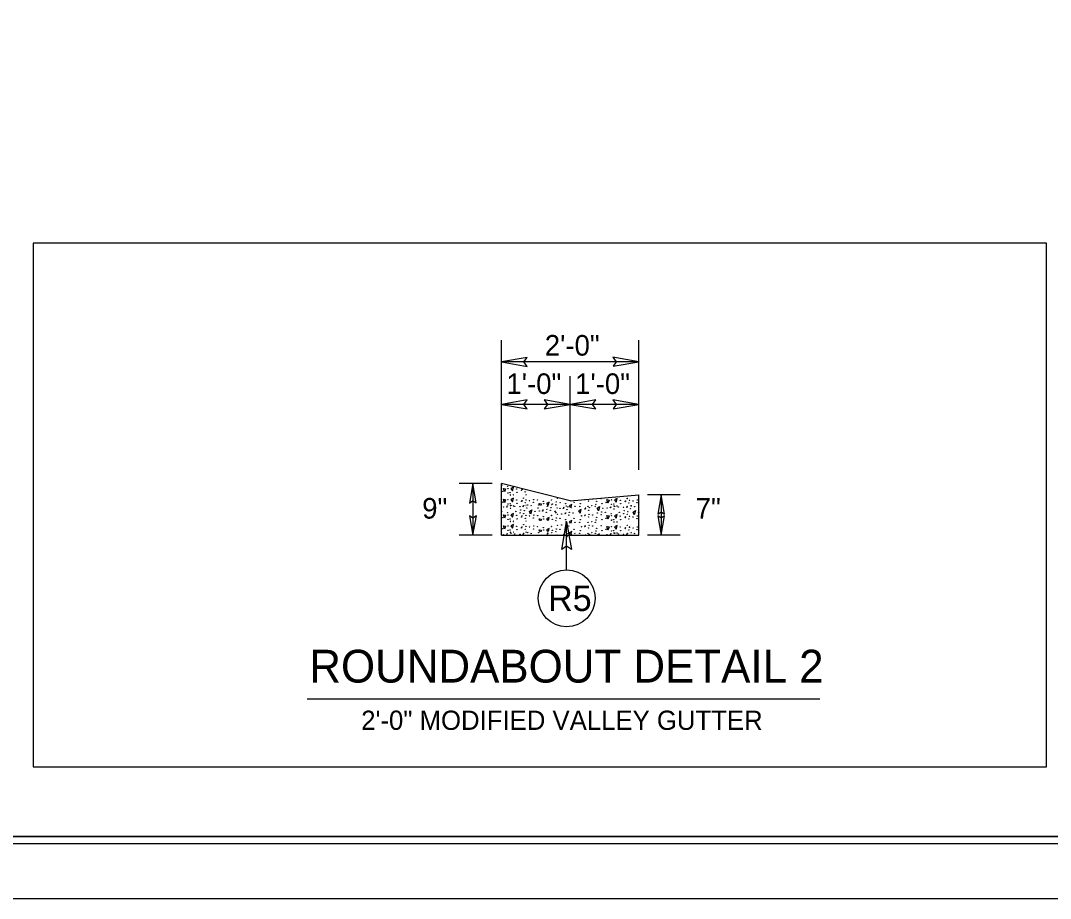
# Model space of a CAD drawing. Extents: x 1640342 to 1730599, y 538663 to 843747.
# Drawn here: x 1730007.8 to 1730082.7, y 538663.2 to 538727.1 of the extents above; entities that cross this region are included whole.
import ezdxf

# ---------------------------------------------------------------- set-up
doc = ezdxf.new("R2010")
doc.units = 0
for name, color, linetype in [('Default', 7, 'Continuous'), ('Sheet Plan CELL', 7, 'Continuous'), ('Sheet Plot Border Inside CELL', 7, 'Continuous'), ('Sheet Plot Border Outside CELL', 7, 'Continuous'), ('Typical Curb CELL', 7, 'Continuous'), ('Typical ID Circle CELL', 7, 'Continuous'), ('Typical Pavement Slope CELL', 7, 'Continuous'), ('Typical Terminator CELL', 7, 'Continuous'), ('Typical Text ID Circle CELL', 7, 'Continuous'), ('Typical Text Label CELL', 7, 'Continuous')]:
    doc.layers.add(name, color=color, linetype=linetype)

msp = doc.modelspace()

# ---------------------------------------------------------------- linework, layer by layer
at = {"layer": 'Default'}
for p, q in [((1730042.739, 538694.39), (1730042.739, 538703.839)), ((1730052.739, 538694.39), (1730052.739, 538703.839)), ((1730052.739, 538702.256), (1730042.739, 538702.256)), ((1730047.739, 538694.39), (1730047.739, 538701.218)), ((1730047.739, 538699.155), (1730042.739, 538699.155)), ((1730052.739, 538699.155), (1730047.739, 538699.155)), ((1730042.062, 538693.39), (1730039.673, 538693.39)), ((1730040.673, 538693.39), (1730040.673, 538689.64)), ((1730055.756, 538692.582), (1730053.367, 538692.582)), ((1730054.367, 538692.582), (1730054.367, 538689.64)), ((1730042.062, 538689.64), (1730039.673, 538689.64)), ((1730055.756, 538689.64), (1730053.367, 538689.64))]:
    msp.add_line(p, q, dxfattribs=at)
for points in [[(1730044.613, 538702.578), (1730042.739, 538702.256), (1730044.624, 538701.922), (1730044.384, 538702.256)], [(1730050.865, 538701.933), (1730052.739, 538702.256), (1730050.855, 538702.589), (1730051.094, 538702.256)], [(1730044.613, 538699.478), (1730042.739, 538699.155), (1730044.624, 538698.822), (1730044.384, 538699.155)], [(1730045.865, 538698.832), (1730047.739, 538699.155), (1730045.855, 538699.488), (1730046.094, 538699.155)], [(1730049.613, 538699.478), (1730047.739, 538699.155), (1730049.624, 538698.822), (1730049.384, 538699.155)], [(1730050.865, 538698.832), (1730052.739, 538699.155), (1730050.855, 538699.488), (1730051.094, 538699.155)], [(1730040.915, 538691.984), (1730040.673, 538693.39), (1730040.423, 538691.977), (1730040.673, 538692.156)], [(1730054.609, 538691.176), (1730054.367, 538692.582), (1730054.117, 538691.168), (1730054.367, 538691.348)], [(1730040.431, 538691.041), (1730040.673, 538689.635), (1730040.923, 538691.049), (1730040.673, 538690.869)], [(1730054.125, 538691.041), (1730054.367, 538689.635), (1730054.617, 538691.049), (1730054.367, 538690.869)]]:
    msp.add_lwpolyline(points, close=True, dxfattribs=at)
at = {"layer": 'Sheet Plan CELL'}
for points in [[(1729873.99, 538667.718), (1729873.985, 538877.713), (1730133.983, 538877.721), (1730133.985, 538847.708), (1730173.993, 538847.706), (1730173.993, 538667.718)], [(1730173.998, 538877.718), (1729873.99, 538877.718), (1729873.99, 538667.718), (1730173.993, 538667.718)]]:
    msp.add_lwpolyline(points, close=True, dxfattribs=at)
at = {"layer": 'Sheet Plot Border Inside CELL'}
msp.add_lwpolyline([(1729843.293, 538667.216), (1730176.49, 538667.218), (1730176.493, 538878.216), (1729843.293, 538878.216)], close=True, dxfattribs=at)
at = {"layer": 'Sheet Plot Border Outside CELL'}
msp.add_lwpolyline([(1729840.693, 538663.216), (1730177.393, 538663.216), (1730177.393, 538882.216), (1729840.693, 538882.216)], close=True, dxfattribs=at)
at = {"layer": 'Typical Curb CELL'}
for p, q in [((1730042.885, 538693.046), (1730043.035, 538693.017)), ((1730042.959, 538692.792), (1730042.885, 538693.046)), ((1730043.035, 538693.017), (1730042.959, 538692.792)), ((1730043.619, 538693.134), (1730043.432, 538693.031)), ((1730043.432, 538693.031), (1730043.553, 538692.863)), ((1730043.553, 538692.863), (1730043.619, 538693.134)), ((1730042.885, 538692.248), (1730043.035, 538692.219)), ((1730042.959, 538691.993), (1730042.885, 538692.248)), ((1730043.035, 538692.219), (1730042.959, 538691.993)), ((1730043.388, 538692.563), (1730043.396, 538692.563)), ((1730043.619, 538692.336), (1730043.432, 538692.233)), ((1730043.432, 538692.233), (1730043.553, 538692.065)), ((1730043.553, 538692.065), (1730043.619, 538692.336)), ((1730043.6, 538692.567), (1730043.621, 538692.567)), ((1730044.514, 538692.586), (1730044.536, 538692.586)), ((1730045.489, 538691.956), (1730045.639, 538691.927)), ((1730045.532, 538691.809), (1730045.489, 538691.956)), ((1730045.639, 538691.927), (1730045.6, 538691.81)), ((1730046.223, 538692.044), (1730046.036, 538691.942)), ((1730046.036, 538691.942), (1730046.123, 538691.821)), ((1730046.169, 538691.822), (1730046.223, 538692.044)), ((1730050.425, 538692.224), (1730050.574, 538692.196)), ((1730050.499, 538691.97), (1730050.425, 538692.224)), ((1730050.574, 538692.196), (1730050.499, 538691.97)), ((1730051.158, 538692.312), (1730050.972, 538692.21)), ((1730050.972, 538692.21), (1730051.093, 538692.042)), ((1730051.093, 538692.042), (1730051.158, 538692.312)), ((1730043.388, 538691.764), (1730043.396, 538691.765)), ((1730043.619, 538691.213), (1730043.432, 538691.111)), ((1730043.553, 538690.943), (1730043.619, 538691.213)), ((1730043.6, 538691.769), (1730043.621, 538691.769)), ((1730044.514, 538691.788), (1730044.536, 538691.788)), ((1730044.786, 538691.367), (1730044.957, 538691.488)), ((1730044.87, 538691.18), (1730044.786, 538691.367)), ((1730044.957, 538691.488), (1730044.87, 538691.18)), ((1730046.603, 538691.417), (1730046.724, 538691.249)), ((1730047.86, 538691.871), (1730047.674, 538691.769)), ((1730047.674, 538691.769), (1730047.741, 538691.675)), ((1730047.813, 538691.676), (1730047.86, 538691.871)), ((1730048.544, 538691.507), (1730048.358, 538691.405)), ((1730048.358, 538691.405), (1730048.479, 538691.237)), ((1730048.479, 538691.237), (1730048.544, 538691.507)), ((1730049.722, 538691.599), (1730049.892, 538691.72)), ((1730049.806, 538691.412), (1730049.722, 538691.599)), ((1730049.892, 538691.72), (1730049.806, 538691.412)), ((1730050.928, 538691.741), (1730050.936, 538691.741)), ((1730051.139, 538691.746), (1730051.16, 538691.746)), ((1730052.054, 538691.765), (1730052.075, 538691.765)), ((1730052.326, 538691.308), (1730052.496, 538691.428)), ((1730052.41, 538691.121), (1730052.326, 538691.308)), ((1730052.496, 538691.428), (1730052.41, 538691.121)), ((1730042.885, 538691.125), (1730043.035, 538691.097)), ((1730042.959, 538690.871), (1730042.885, 538691.125)), ((1730043.035, 538691.097), (1730042.959, 538690.871)), ((1730043.388, 538690.642), (1730043.396, 538690.642)), ((1730043.432, 538691.111), (1730043.553, 538690.943)), ((1730043.6, 538690.647), (1730043.621, 538690.647)), ((1730044.514, 538690.666), (1730044.536, 538690.666)), ((1730045.489, 538690.834), (1730045.639, 538690.805)), ((1730045.532, 538690.687), (1730045.489, 538690.834)), ((1730045.639, 538690.805), (1730045.6, 538690.688)), ((1730046.223, 538690.922), (1730046.036, 538690.82)), ((1730046.036, 538690.82), (1730046.123, 538690.699)), ((1730046.169, 538690.7), (1730046.223, 538690.922)), ((1730047.86, 538690.713), (1730047.674, 538690.61)), ((1730047.674, 538690.61), (1730047.741, 538690.517)), ((1730047.813, 538690.518), (1730047.86, 538690.713)), ((1730050.425, 538691.066), (1730050.574, 538691.037)), ((1730050.499, 538690.812), (1730050.425, 538691.066)), ((1730050.574, 538691.037), (1730050.499, 538690.812)), ((1730050.928, 538690.583), (1730050.936, 538690.583)), ((1730051.158, 538691.154), (1730050.972, 538691.052)), ((1730050.972, 538691.052), (1730051.093, 538690.884)), ((1730051.093, 538690.884), (1730051.158, 538691.154)), ((1730051.139, 538690.587), (1730051.16, 538690.588)), ((1730052.054, 538690.606), (1730052.075, 538690.607)), ((1730042.885, 538690.327), (1730043.035, 538690.298)), ((1730042.959, 538690.073), (1730042.885, 538690.327)), ((1730043.035, 538690.298), (1730042.959, 538690.073)), ((1730043.388, 538689.844), (1730043.396, 538689.844)), ((1730043.619, 538690.415), (1730043.432, 538690.313)), ((1730043.432, 538690.313), (1730043.553, 538690.145)), ((1730043.553, 538690.145), (1730043.619, 538690.415)), ((1730043.6, 538689.848), (1730043.621, 538689.849)), ((1730044.514, 538689.867), (1730044.536, 538689.868)), ((1730045.489, 538690.036), (1730045.639, 538690.007)), ((1730045.532, 538689.889), (1730045.489, 538690.036)), ((1730045.639, 538690.007), (1730045.6, 538689.89)), ((1730046.223, 538690.124), (1730046.036, 538690.021)), ((1730046.036, 538690.021), (1730046.123, 538689.901)), ((1730046.169, 538689.902), (1730046.223, 538690.124)), ((1730047.86, 538689.915), (1730047.674, 538689.812)), ((1730047.674, 538689.812), (1730047.741, 538689.719)), ((1730047.813, 538689.72), (1730047.86, 538689.915)), ((1730049.722, 538689.643), (1730049.892, 538689.764)), ((1730050.425, 538690.268), (1730050.574, 538690.239)), ((1730050.499, 538690.014), (1730050.425, 538690.268)), ((1730050.574, 538690.239), (1730050.499, 538690.014)), ((1730050.928, 538689.785), (1730050.936, 538689.785)), ((1730051.158, 538690.356), (1730050.972, 538690.254)), ((1730050.972, 538690.254), (1730051.093, 538690.086)), ((1730051.093, 538690.086), (1730051.158, 538690.356)), ((1730051.139, 538689.789), (1730051.16, 538689.79)), ((1730052.054, 538689.808), (1730052.075, 538689.809))]:
    msp.add_line(p, q, dxfattribs=at)
for centre in [(1730042.772, 538693.279), (1730042.819, 538692.839), (1730043.184, 538693.195), (1730043.216, 538693.031), (1730043.216, 538692.713), (1730043.375, 538692.741), (1730043.852, 538693.003), (1730043.881, 538692.75), (1730044.212, 538692.893), (1730044.244, 538692.953), (1730044.478, 538692.794), (1730042.819, 538692.041), (1730043.216, 538692.233), (1730043.216, 538691.915), (1730043.375, 538691.943), (1730043.852, 538692.205), (1730043.881, 538691.952), (1730044.212, 538692.095), (1730044.244, 538692.155), (1730044.358, 538692.333), (1730044.478, 538691.996), (1730044.525, 538692.202), (1730044.787, 538692.152), (1730045.068, 538692.021), (1730045.096, 538692.217), (1730045.376, 538692.19), (1730045.788, 538692.105), (1730045.821, 538691.941), (1730046.391, 538692.194), (1730046.457, 538691.913), (1730046.733, 538692.044), (1730046.827, 538692.316), (1730047.014, 538692.016), (1730047.425, 538691.932), (1730048.029, 538692.02), (1730048.493, 538691.932), (1730048.813, 538692.215), (1730049.079, 538692.117), (1730049.379, 538692.267), (1730049.668, 538692.1), (1730050.003, 538692.289), (1730050.059, 538691.934), (1730050.359, 538692.018), (1730050.756, 538692.209), (1730050.915, 538691.919), (1730051.392, 538692.181), (1730051.42, 538691.929), (1730051.752, 538692.071), (1730051.784, 538692.132), (1730051.897, 538692.309), (1730052.018, 538691.973), (1730052.065, 538692.179), (1730052.327, 538692.129), (1730052.607, 538691.998), (1730052.635, 538692.194), (1730042.772, 538691.359), (1730042.894, 538691.686), (1730043.137, 538691.695), (1730043.169, 538691.756), (1730043.184, 538691.274), (1730043.404, 538691.597), (1730043.45, 538691.803), (1730043.703, 538691.747), (1730043.787, 538691.363), (1730044.089, 538691.717), (1730044.1, 538691.266), (1730044.147, 538691.472), (1730044.333, 538691.726), (1730044.358, 538691.21), (1730044.365, 538691.787), (1730044.404, 538691.416), (1730044.599, 538691.627), (1730044.646, 538691.833), (1730044.898, 538691.777), (1730045.189, 538691.366), (1730045.404, 538691.625), (1730045.451, 538691.83), (1730045.498, 538691.394), (1730045.741, 538691.404), (1730045.774, 538691.464), (1730046.008, 538691.305), (1730046.054, 538691.511), (1730046.088, 538691.741), (1730046.12, 538691.802), (1730046.307, 538691.455), (1730046.354, 538691.643), (1730046.401, 538691.849), (1730046.705, 538691.848), (1730046.799, 538691.61), (1730047.013, 538691.586), (1730047.136, 538691.185), (1730047.256, 538691.596), (1730047.289, 538691.656), (1730047.379, 538691.195), (1730047.411, 538691.255), (1730047.458, 538691.768), (1730047.523, 538691.497), (1730047.569, 538691.703), (1730047.692, 538691.302), (1730047.822, 538691.647), (1730047.944, 538691.246), (1730048.094, 538691.74), (1730048.446, 538691.727), (1730048.829, 538691.543), (1730048.862, 538691.603), (1730049.041, 538691.737), (1730049.096, 538691.444), (1730049.126, 538691.164), (1730049.142, 538691.65), (1730049.322, 538691.784), (1730049.574, 538691.728), (1730049.621, 538691.895), (1730049.722, 538691.262), (1730050.031, 538691.327), (1730050.125, 538691.599), (1730050.312, 538691.3), (1730050.434, 538691.627), (1730050.677, 538691.636), (1730050.709, 538691.697), (1730050.723, 538691.215), (1730050.756, 538691.891), (1730050.943, 538691.538), (1730050.99, 538691.743), (1730051.243, 538691.687), (1730051.327, 538691.304), (1730051.629, 538691.658), (1730051.64, 538691.207), (1730051.687, 538691.413), (1730051.872, 538691.667), (1730051.905, 538691.727), (1730051.944, 538691.357), (1730052.139, 538691.568), (1730052.186, 538691.774), (1730052.438, 538691.718), (1730052.729, 538691.307), (1730042.819, 538690.919), (1730043.216, 538691.11), (1730043.216, 538690.792), (1730043.375, 538690.82), (1730043.852, 538691.082), (1730043.881, 538690.83), (1730044.212, 538690.972), (1730044.244, 538691.033), (1730044.478, 538690.874), (1730044.525, 538691.08), (1730044.787, 538691.03), (1730045.068, 538690.899), (1730045.096, 538691.095), (1730045.376, 538691.067), (1730045.788, 538690.983), (1730045.821, 538690.819), (1730046.391, 538691.071), (1730046.457, 538690.791), (1730046.705, 538690.689), (1730046.733, 538690.886), (1730046.827, 538691.157), (1730047.014, 538690.858), (1730047.425, 538690.774), (1730047.458, 538690.61), (1730047.645, 538691.096), (1730048.029, 538690.862), (1730048.094, 538690.582), (1730048.446, 538690.568), (1730048.493, 538690.774), (1730048.57, 538691.048), (1730048.813, 538691.057), (1730048.845, 538691.118), (1730049.041, 538690.579), (1730049.079, 538690.958), (1730049.322, 538690.626), (1730049.379, 538691.108), (1730049.574, 538690.57), (1730049.621, 538690.736), (1730049.668, 538690.942), (1730050.003, 538691.131), (1730050.059, 538690.775), (1730050.359, 538690.86), (1730050.756, 538691.051), (1730050.756, 538690.733), (1730050.915, 538690.761), (1730051.392, 538691.023), (1730051.42, 538690.771), (1730051.752, 538690.913), (1730051.784, 538690.974), (1730051.897, 538691.151), (1730052.018, 538690.815), (1730052.065, 538691.02), (1730052.327, 538690.971), (1730052.607, 538690.839), (1730052.635, 538691.036), (1730042.819, 538690.121), (1730042.894, 538689.67), (1730043.137, 538689.68), (1730043.169, 538689.74), (1730043.216, 538690.312), (1730043.216, 538689.994), (1730043.375, 538690.022), (1730043.45, 538689.787), (1730043.703, 538689.731), (1730043.852, 538690.284), (1730043.881, 538690.032), (1730044.089, 538689.701), (1730044.212, 538690.174), (1730044.244, 538690.235), (1730044.333, 538689.711), (1730044.358, 538690.412), (1730044.365, 538689.771), (1730044.478, 538690.076), (1730044.525, 538690.281), (1730044.646, 538689.818), (1730044.787, 538690.232), (1730044.898, 538689.762), (1730045.068, 538690.1), (1730045.096, 538690.297), (1730045.376, 538690.269), (1730045.451, 538689.815), (1730045.788, 538690.185), (1730045.821, 538690.021), (1730046.088, 538689.726), (1730046.12, 538689.786), (1730046.391, 538690.273), (1730046.401, 538689.833), (1730046.457, 538689.993), (1730046.705, 538689.891), (1730046.733, 538690.088), (1730046.827, 538690.359), (1730047.014, 538690.06), (1730047.136, 538690.387), (1730047.289, 538689.7), (1730047.425, 538689.976), (1730047.458, 538689.812), (1730047.569, 538689.747), (1730047.645, 538690.298), (1730047.822, 538689.691), (1730048.029, 538690.064), (1730048.094, 538689.784), (1730048.446, 538689.77), (1730048.493, 538689.976), (1730048.57, 538690.25), (1730048.813, 538690.259), (1730048.845, 538690.319), (1730049.041, 538689.781), (1730049.079, 538690.16), (1730049.126, 538690.366), (1730049.142, 538689.693), (1730049.322, 538689.827), (1730049.379, 538690.31), (1730049.574, 538689.771), (1730049.621, 538689.938), (1730049.668, 538690.144), (1730050.003, 538690.333), (1730050.059, 538689.977), (1730050.359, 538690.061), (1730050.434, 538689.67), (1730050.677, 538689.68), (1730050.709, 538689.74), (1730050.756, 538690.253), (1730050.756, 538689.935), (1730050.915, 538689.963), (1730050.99, 538689.787), (1730051.243, 538689.731), (1730051.392, 538690.225), (1730051.42, 538689.972), (1730051.629, 538689.701), (1730051.752, 538690.115), (1730051.784, 538690.176), (1730051.872, 538689.711), (1730051.897, 538690.353), (1730051.905, 538689.771), (1730052.018, 538690.016), (1730052.065, 538690.222), (1730052.186, 538689.818), (1730052.327, 538690.172), (1730052.438, 538689.762), (1730052.607, 538690.041), (1730052.635, 538690.238), (1730046.799, 538689.654), (1730047.523, 538689.541), (1730048.862, 538689.647)]:
    msp.add_circle(centre, 0.0131, dxfattribs=at)
for centre, start, end in [((1730043.392, 538692.575), 287.79478, 254.59053), ((1730043.61, 538692.575), 323.39792, 218.98739), ((1730044.525, 538692.579), 36.13839, 146.24692), ((1730043.392, 538691.777), 287.79478, 254.59053), ((1730043.61, 538691.777), 323.39792, 218.98739), ((1730044.525, 538691.781), 36.13839, 146.24692), ((1730050.932, 538691.754), 287.79478, 254.59053), ((1730051.15, 538691.754), 323.39792, 218.98739), ((1730052.065, 538691.757), 36.13839, 146.24692), ((1730043.392, 538690.655), 287.79478, 254.59053), ((1730043.61, 538690.655), 323.39792, 218.98739), ((1730044.525, 538690.658), 36.13839, 146.24692), ((1730050.932, 538690.596), 287.79478, 254.59053), ((1730051.15, 538690.596), 323.39792, 218.98739), ((1730052.065, 538690.599), 36.13839, 146.24692), ((1730043.392, 538689.857), 287.79478, 254.59053), ((1730043.61, 538689.857), 323.39792, 218.98739), ((1730044.525, 538689.86), 36.13839, 146.24692), ((1730050.932, 538689.798), 287.79478, 254.59053), ((1730051.15, 538689.798), 323.39792, 218.98739), ((1730052.065, 538689.801), 36.13839, 146.24692)]:
    msp.add_arc(centre, 0.0131, start, end, dxfattribs=at)
at = {"layer": 'Typical ID Circle CELL'}
msp.add_line((1730047.491, 538687.122), (1730047.491, 538690.608), dxfattribs=at)
msp.add_circle((1730047.492, 538685.051), 2.071, dxfattribs=at)
at = {"layer": 'Typical Pavement Slope CELL'}
for p, q in [((1730042.739, 538689.64), (1730042.739, 538693.39)), ((1730047.739, 538692.14), (1730042.739, 538693.39)), ((1730047.739, 538692.14), (1730052.739, 538692.582)), ((1730052.739, 538689.64), (1730052.739, 538692.582)), ((1730042.739, 538689.64), (1730052.739, 538689.64))]:
    msp.add_line(p, q, dxfattribs=at)
at = {"layer": 'Typical Terminator CELL'}
msp.add_lwpolyline([(1730047.145, 538688.6), (1730047.491, 538690.608), (1730047.848, 538688.589), (1730047.491, 538688.846)], close=True, dxfattribs=at)
at = {"layer": 'Typical Text Label CELL'}
msp.add_line((1730028.603, 538677.729), (1730065.91, 538677.729), dxfattribs=at)
msp.add_lwpolyline([(1730008.672, 538672.777), (1730082.404, 538672.777), (1730082.404, 538710.888), (1730008.672, 538710.888)], close=True, dxfattribs=at)

# ---------------------------------------------------------------- texts
at = {"layer": 'Default'}
for s, p in [('2\'-0"', (1730045.9, 538702.702)), ('1\'-0"', (1730043.107, 538699.911)), ('1\'-0"', (1730048.107, 538699.911)), ('9"', (1730036.978, 538690.845)), ('7"', (1730056.881, 538690.845))]:
    msp.add_text(s, height=1.5, dxfattribs=at).set_placement(p)
at = {"layer": 'Typical Text ID Circle CELL'}
msp.add_text('R5', height=1.8535, dxfattribs=at).set_placement((1730046.142, 538684.125))
at = {"layer": 'Typical Text Label CELL'}
for s, height, p in [('ROUNDABOUT DETAIL 2', 2.38712, (1730028.762, 538678.916)), ('2\'-0" MODIFIED VALLEY GUTTER', 1.4, (1730032.541, 538675.476))]:
    msp.add_text(s, height=height, dxfattribs=at).set_placement(p)

doc.saveas('drawing.dxf')
